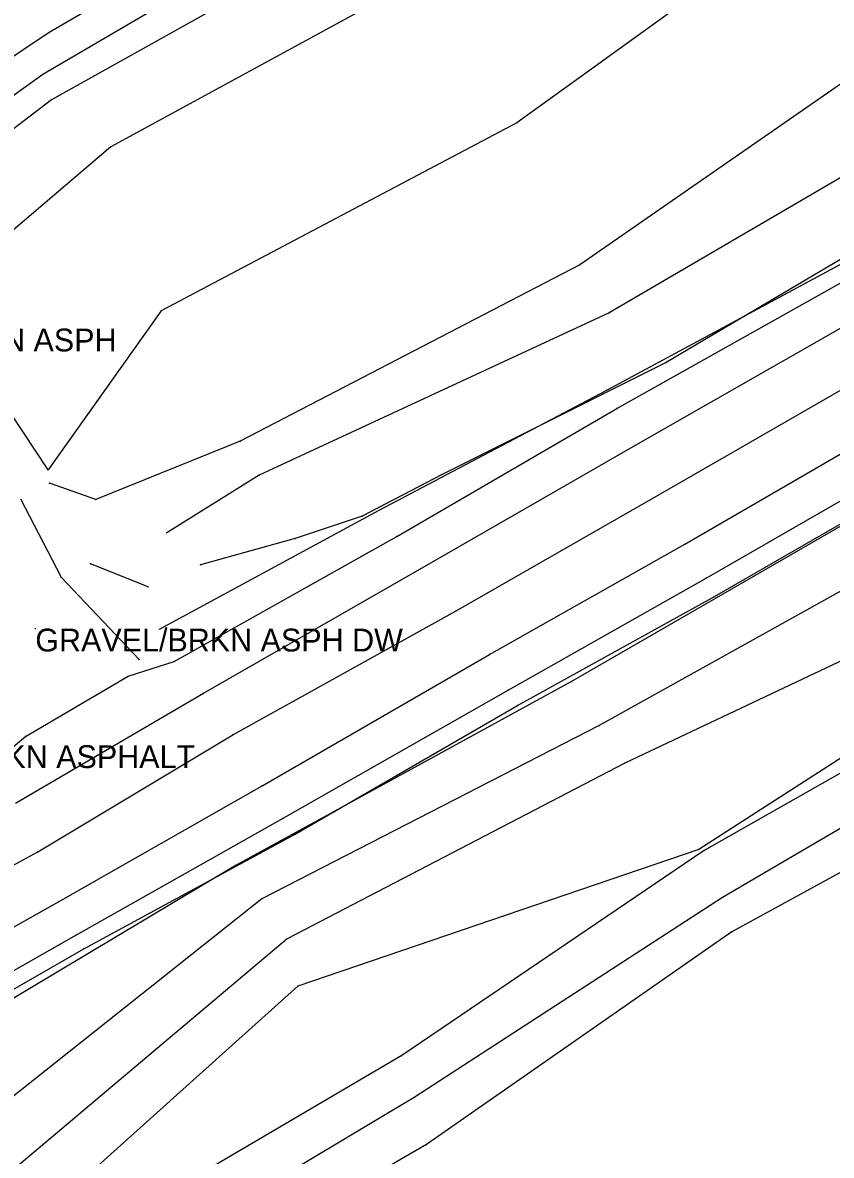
# Model space of a CAD drawing. Extents: x 1419505 to 1434054, y 1956910 to 1968644.
# Drawn here: x 1423426 to 1423603.3, y 1959101.1 to 1959349.3 of the extents above; entities that cross this region are included whole.
import ezdxf

# ---------------------------------------------------------------- set-up
doc = ezdxf.new("R2010")
doc.units = 0
for name, color, linetype in [('S_BREAKLINE', 7, 'Continuous'), ('S_DITCHLINE', 7, 'Continuous'), ('S_DRIVEWAY', 7, 'Continuous'), ('S_DRIVEWAY_ANNOT', 7, 'Continuous'), ('S_EDGE_PAVEMENT', 7, 'Continuous'), ('S_GRD_PT_SYM', 7, 'Continuous'), ('S_MSC_PT_SYM', 7, 'Continuous'), ('S_PAVEMENT_CROWN', 7, 'Continuous'), ('S_RDW_PT_SYM', 7, 'Continuous'), ('S_SHOULDER', 7, 'Continuous'), ('S_SURVEY_TEXT_ANNOT', 7, 'Continuous')]:
    doc.layers.add(name, color=color, linetype=linetype)

msp = doc.modelspace()

# ---------------------------------------------------------------- linework, layer by layer
at = {"layer": 'S_BREAKLINE'}
for p, q in [((1423507.0107, 1959374.1404), (1423432.3018, 1959332.4447)), ((1423598.1405, 1959373.3034), (1423534.3444, 1959327.3684)), ((1423515.8552, 1959360.5385), (1423445.3007, 1959322.0911)), ((1423617.2978, 1959344.1385), (1423548.1653, 1959296.2644)), ((1423432.3018, 1959332.4447), (1423394.0694, 1959303.2168)), ((1423534.3444, 1959327.3684), (1423456.3434, 1959286.1857)), ((1423625.4253, 1959327.0984), (1423554.6027, 1959285.7077)), ((1423445.3007, 1959322.0911), (1423416.7178, 1959297.7635)), ((1423633.4068, 1959314.0375), (1423567.1095, 1959274.87)), ((1423554.0877, 1959268.7666), (1423610.4613, 1959299.1086)), ((1423548.1653, 1959296.2644), (1423473.6845, 1959257.5739)), ((1423456.3434, 1959286.1857), (1423431.5548, 1959251.3445)), ((1423554.6027, 1959285.7077), (1423477.8778, 1959250.1254)), ((1423431.5548, 1959251.3445), (1423409.3454, 1959284.8777)), ((1423567.1095, 1959274.87), (1423517.9574, 1959250.2694)), ((1423504.1975, 1959242.4739), (1423554.0877, 1959268.7666)), ((1423473.6845, 1959257.5739), (1423442.0165, 1959244.8561)), ((1423627.3024, 1959251.6155), (1423546.3592, 1959204.9295)), ((1423577.7382, 1959223.5517), (1423626.5424, 1959251.6805)), ((1423442.0165, 1959244.8561), (1423431.8328, 1959248.4073)), ((1423477.8778, 1959250.1254), (1423457.5655, 1959237.5506)), ((1423517.9574, 1959250.2694), (1423500.4342, 1959241.1398)), ((1423456.0254, 1959216.4252), (1423504.1975, 1959242.4739)), ((1423500.4342, 1959241.1398), (1423485.7493, 1959236.3075)), ((1423633.2968, 1959240.3308), (1423552.4576, 1959195.2769)), ((1423485.7493, 1959236.3075), (1423465.0039, 1959230.4911)), ((1423453.4842, 1959225.6568), (1423440.8484, 1959230.7452)), ((1423642.5494, 1959226.9049), (1423558.039, 1959187.0693)), ((1423534.5064, 1959199.6852), (1423577.7382, 1959223.5517)), ((1423546.3592, 1959204.9295), (1423472.7794, 1959164.6929)), ((1423655.6463, 1959202.1823), (1423579.4483, 1959157.5964)), ((1423485.5793, 1959171.3943), (1423534.5064, 1959199.6852)), ((1423552.4576, 1959195.2769), (1423478.4158, 1959157.2674)), ((1423661.9817, 1959194.0338), (1423581.5465, 1959150.057)), ((1423558.039, 1959187.0693), (1423483.9612, 1959148.5579)), ((1423439.3733, 1959146.3467), (1423485.5793, 1959171.3943)), ((1423472.7794, 1959164.6929), (1423404.08, 1959123.6312)), ((1423478.4158, 1959157.2674), (1423414.3837, 1959106.4521)), ((1423579.4483, 1959157.5964), (1423511.876, 1959113.7706)), ((1423581.5465, 1959150.057), (1423514.5431, 1959103.4839)), ((1423412.8916, 1959131.0967), (1423439.3733, 1959146.3467)), ((1423483.9612, 1959148.5579), (1423419.455, 1959094.2393)), ((1423511.876, 1959113.7706), (1423435.8811, 1959068.4857)), ((1423514.5431, 1959103.4839), (1423441.2794, 1959060.9832))]:
    msp.add_line(p, q, dxfattribs=at)
at = {"layer": 'S_DITCHLINE'}
for p, q in [((1423500.8393, 1959387.3443), (1423431.7848, 1959347.1597)), ((1423503.4494, 1959380.6948), (1423430.4317, 1959337.9941)), ((1423431.7848, 1959347.1597), (1423383.7177, 1959315.2086)), ((1423430.4317, 1959337.9941), (1423390.0321, 1959308.9862)), ((1423648.1638, 1959215.5822), (1423574.263, 1959168.1471)), ((1423651.375, 1959211.0559), (1423575.4791, 1959167.9211)), ((1423574.263, 1959168.1471), (1423486.2963, 1959138.1412)), ((1423575.4791, 1959167.9211), (1423509.1638, 1959122.9912)), ((1423486.2963, 1959138.1412), (1423426.1714, 1959084.2167)), ((1423509.1638, 1959122.9912), (1423431.0428, 1959077.1912))]:
    msp.add_line(p, q, dxfattribs=at)
at = {"layer": 'S_DRIVEWAY'}
for p, q in [((1423425.4984, 1959244.9341), (1423434.41, 1959227.774)), ((1423434.41, 1959227.774), (1423451.4981, 1959209.7318))]:
    msp.add_line(p, q, dxfattribs=at)
at = {"layer": 'S_EDGE_PAVEMENT'}
for p, q in [((1423560.4201, 1959256.7308), (1423615.9457, 1959288.4599)), ((1423571.2408, 1959235.0654), (1423620.903, 1959263.7863)), ((1423513.1051, 1959229.5281), (1423560.4201, 1959256.7308)), ((1423528.338, 1959210.8249), (1423571.2408, 1959235.0654)), ((1423465.613, 1959202.4093), (1423513.1051, 1959229.5281)), ((1423478.4798, 1959182.074), (1423528.338, 1959210.8249)), ((1423424.3883, 1959178.2548), (1423465.613, 1959202.4093)), ((1423433.8469, 1959156.6184), (1423478.4798, 1959182.074)), ((1423406.3952, 1959141.3454), (1423433.8469, 1959156.6184))]:
    msp.add_line(p, q, dxfattribs=at)
at = {"layer": 'S_GRD_PT_SYM'}
for points in [[(1423431.7848, 1959347.1597), (1423431.7848, 1959347.2097), (1423431.7848, 1959347.1597), (1423431.7348, 1959347.1597), (1423431.7848, 1959347.1597), (1423431.7848, 1959347.1097), (1423431.7848, 1959347.1597), (1423431.8348, 1959347.1597)], [(1423430.4317, 1959337.9941), (1423430.4317, 1959338.0441), (1423430.4317, 1959337.9941), (1423430.3817, 1959337.9941), (1423430.4317, 1959337.9941), (1423430.4317, 1959337.9441), (1423430.4317, 1959337.9941), (1423430.4817, 1959337.9941)], [(1423432.3018, 1959332.4447), (1423432.3018, 1959332.4947), (1423432.3018, 1959332.4447), (1423432.2518, 1959332.4447), (1423432.3018, 1959332.4447), (1423432.3018, 1959332.3947), (1423432.3018, 1959332.4447), (1423432.3518, 1959332.4447)], [(1423534.3444, 1959327.3684), (1423534.3444, 1959327.4184), (1423534.3444, 1959327.3684), (1423534.2944, 1959327.3684), (1423534.3444, 1959327.3684), (1423534.3444, 1959327.3184), (1423534.3444, 1959327.3684), (1423534.3944, 1959327.3684)], [(1423445.3007, 1959322.0911), (1423445.3007, 1959322.1411), (1423445.3007, 1959322.0911), (1423445.2507, 1959322.0911), (1423445.3007, 1959322.0911), (1423445.3007, 1959322.0411), (1423445.3007, 1959322.0911), (1423445.3507, 1959322.0911)], [(1423548.1653, 1959296.2644), (1423548.1653, 1959296.3144), (1423548.1653, 1959296.2644), (1423548.1153, 1959296.2644), (1423548.1653, 1959296.2644), (1423548.1653, 1959296.2144), (1423548.1653, 1959296.2644), (1423548.2153, 1959296.2644)], [(1423456.3434, 1959286.1857), (1423456.3434, 1959286.2357), (1423456.3434, 1959286.1857), (1423456.2934, 1959286.1857), (1423456.3434, 1959286.1857), (1423456.3434, 1959286.1357), (1423456.3434, 1959286.1857), (1423456.3934, 1959286.1857)], [(1423554.6027, 1959285.7077), (1423554.6027, 1959285.7577), (1423554.6027, 1959285.7077), (1423554.5527, 1959285.7077), (1423554.6027, 1959285.7077), (1423554.6027, 1959285.6577), (1423554.6027, 1959285.7077), (1423554.6527, 1959285.7077)], [(1423567.1095, 1959274.87), (1423567.1095, 1959274.92), (1423567.1095, 1959274.87), (1423567.0595, 1959274.87), (1423567.1095, 1959274.87), (1423567.1095, 1959274.82), (1423567.1095, 1959274.87), (1423567.1595, 1959274.87)], [(1423554.0877, 1959268.7666), (1423554.0877, 1959268.8166), (1423554.0877, 1959268.7666), (1423554.0377, 1959268.7666), (1423554.0877, 1959268.7666), (1423554.0877, 1959268.7166), (1423554.0877, 1959268.7666), (1423554.1377, 1959268.7666)], [(1423473.6845, 1959257.5739), (1423473.6845, 1959257.6239), (1423473.6845, 1959257.5739), (1423473.6345, 1959257.5739), (1423473.6845, 1959257.5739), (1423473.6845, 1959257.5239), (1423473.6845, 1959257.5739), (1423473.7345, 1959257.5739)], [(1423431.5548, 1959251.3445), (1423431.5548, 1959251.3945), (1423431.5548, 1959251.3445), (1423431.5048, 1959251.3445), (1423431.5548, 1959251.3445), (1423431.5548, 1959251.2945), (1423431.5548, 1959251.3445), (1423431.6048, 1959251.3445)], [(1423431.8328, 1959248.4073), (1423431.8328, 1959248.4573), (1423431.8328, 1959248.4073), (1423431.7828, 1959248.4073), (1423431.8328, 1959248.4073), (1423431.8328, 1959248.3573), (1423431.8328, 1959248.4073), (1423431.8828, 1959248.4073)], [(1423477.8778, 1959250.1254), (1423477.8778, 1959250.1754), (1423477.8778, 1959250.1254), (1423477.8278, 1959250.1254), (1423477.8778, 1959250.1254), (1423477.8778, 1959250.0754), (1423477.8778, 1959250.1254), (1423477.9278, 1959250.1254)], [(1423517.9574, 1959250.2694), (1423517.9574, 1959250.3194), (1423517.9574, 1959250.2694), (1423517.9074, 1959250.2694), (1423517.9574, 1959250.2694), (1423517.9574, 1959250.2194), (1423517.9574, 1959250.2694), (1423518.0074, 1959250.2694)], [(1423442.0165, 1959244.8561), (1423442.0165, 1959244.9061), (1423442.0165, 1959244.8561), (1423441.9665, 1959244.8561), (1423442.0165, 1959244.8561), (1423442.0165, 1959244.8061), (1423442.0165, 1959244.8561), (1423442.0665, 1959244.8561)], [(1423500.4342, 1959241.1398), (1423500.4342, 1959241.1898), (1423500.4342, 1959241.1398), (1423500.3842, 1959241.1398), (1423500.4342, 1959241.1398), (1423500.4342, 1959241.0898), (1423500.4342, 1959241.1398), (1423500.4842, 1959241.1398)], [(1423504.1975, 1959242.4739), (1423504.1975, 1959242.5239), (1423504.1975, 1959242.4739), (1423504.1475, 1959242.4739), (1423504.1975, 1959242.4739), (1423504.1975, 1959242.4239), (1423504.1975, 1959242.4739), (1423504.2475, 1959242.4739)], [(1423457.5655, 1959237.5506), (1423457.5655, 1959237.6006), (1423457.5655, 1959237.5506), (1423457.5155, 1959237.5506), (1423457.5655, 1959237.5506), (1423457.5655, 1959237.5006), (1423457.5655, 1959237.5506), (1423457.6155, 1959237.5506)], [(1423485.7493, 1959236.3075), (1423485.7493, 1959236.3575), (1423485.7493, 1959236.3075), (1423485.6993, 1959236.3075), (1423485.7493, 1959236.3075), (1423485.7493, 1959236.2575), (1423485.7493, 1959236.3075), (1423485.7993, 1959236.3075)], [(1423440.8484, 1959230.7452), (1423440.8484, 1959230.7952), (1423440.8484, 1959230.7452), (1423440.7984, 1959230.7452), (1423440.8484, 1959230.7452), (1423440.8484, 1959230.6952), (1423440.8484, 1959230.7452), (1423440.8984, 1959230.7452)], [(1423465.0039, 1959230.4911), (1423465.0039, 1959230.5411), (1423465.0039, 1959230.4911), (1423464.9539, 1959230.4911), (1423465.0039, 1959230.4911), (1423465.0039, 1959230.4411), (1423465.0039, 1959230.4911), (1423465.0539, 1959230.4911)], [(1423453.4842, 1959225.6568), (1423453.4842, 1959225.7068), (1423453.4842, 1959225.6568), (1423453.4342, 1959225.6568), (1423453.4842, 1959225.6568), (1423453.4842, 1959225.6068), (1423453.4842, 1959225.6568), (1423453.5342, 1959225.6568)], [(1423577.7382, 1959223.5517), (1423577.7382, 1959223.6017), (1423577.7382, 1959223.5517), (1423577.6882, 1959223.5517), (1423577.7382, 1959223.5517), (1423577.7382, 1959223.5017), (1423577.7382, 1959223.5517), (1423577.7882, 1959223.5517)], [(1423456.0254, 1959216.4252), (1423456.0254, 1959216.4752), (1423456.0254, 1959216.4252), (1423455.9754, 1959216.4252), (1423456.0254, 1959216.4252), (1423456.0254, 1959216.3752), (1423456.0254, 1959216.4252), (1423456.0754, 1959216.4252)], [(1423546.3592, 1959204.9295), (1423546.3592, 1959204.9795), (1423546.3592, 1959204.9295), (1423546.3092, 1959204.9295), (1423546.3592, 1959204.9295), (1423546.3592, 1959204.8795), (1423546.3592, 1959204.9295), (1423546.4092, 1959204.9295)], [(1423534.5064, 1959199.6852), (1423534.5064, 1959199.7352), (1423534.5064, 1959199.6852), (1423534.4564, 1959199.6852), (1423534.5064, 1959199.6852), (1423534.5064, 1959199.6352), (1423534.5064, 1959199.6852), (1423534.5564, 1959199.6852)], [(1423552.4576, 1959195.2769), (1423552.4576, 1959195.3269), (1423552.4576, 1959195.2769), (1423552.4076, 1959195.2769), (1423552.4576, 1959195.2769), (1423552.4576, 1959195.2269), (1423552.4576, 1959195.2769), (1423552.5076, 1959195.2769)], [(1423558.039, 1959187.0693), (1423558.039, 1959187.1193), (1423558.039, 1959187.0693), (1423557.989, 1959187.0693), (1423558.039, 1959187.0693), (1423558.039, 1959187.0193), (1423558.039, 1959187.0693), (1423558.089, 1959187.0693)], [(1423485.5793, 1959171.3943), (1423485.5793, 1959171.4443), (1423485.5793, 1959171.3943), (1423485.5293, 1959171.3943), (1423485.5793, 1959171.3943), (1423485.5793, 1959171.3443), (1423485.5793, 1959171.3943), (1423485.6293, 1959171.3943)], [(1423574.263, 1959168.1471), (1423574.263, 1959168.1971), (1423574.263, 1959168.1471), (1423574.213, 1959168.1471), (1423574.263, 1959168.1471), (1423574.263, 1959168.0971), (1423574.263, 1959168.1471), (1423574.313, 1959168.1471)], [(1423575.4791, 1959167.9211), (1423575.4791, 1959167.9711), (1423575.4791, 1959167.9211), (1423575.4291, 1959167.9211), (1423575.4791, 1959167.9211), (1423575.4791, 1959167.8711), (1423575.4791, 1959167.9211), (1423575.5291, 1959167.9211)], [(1423472.7794, 1959164.6929), (1423472.7794, 1959164.7429), (1423472.7794, 1959164.6929), (1423472.7294, 1959164.6929), (1423472.7794, 1959164.6929), (1423472.7794, 1959164.6429), (1423472.7794, 1959164.6929), (1423472.8294, 1959164.6929)], [(1423478.4158, 1959157.2674), (1423478.4158, 1959157.3174), (1423478.4158, 1959157.2674), (1423478.3658, 1959157.2674), (1423478.4158, 1959157.2674), (1423478.4158, 1959157.2174), (1423478.4158, 1959157.2674), (1423478.4658, 1959157.2674)], [(1423579.4483, 1959157.5964), (1423579.4483, 1959157.6464), (1423579.4483, 1959157.5964), (1423579.3983, 1959157.5964), (1423579.4483, 1959157.5964), (1423579.4483, 1959157.5464), (1423579.4483, 1959157.5964), (1423579.4983, 1959157.5964)], [(1423581.5465, 1959150.057), (1423581.5465, 1959150.107), (1423581.5465, 1959150.057), (1423581.4965, 1959150.057), (1423581.5465, 1959150.057), (1423581.5465, 1959150.007), (1423581.5465, 1959150.057), (1423581.5965, 1959150.057)], [(1423439.3733, 1959146.3467), (1423439.3733, 1959146.3967), (1423439.3733, 1959146.3467), (1423439.3233, 1959146.3467), (1423439.3733, 1959146.3467), (1423439.3733, 1959146.2967), (1423439.3733, 1959146.3467), (1423439.4233, 1959146.3467)], [(1423483.9612, 1959148.5579), (1423483.9612, 1959148.6079), (1423483.9612, 1959148.5579), (1423483.9112, 1959148.5579), (1423483.9612, 1959148.5579), (1423483.9612, 1959148.5079), (1423483.9612, 1959148.5579), (1423484.0112, 1959148.5579)], [(1423486.2963, 1959138.1412), (1423486.2963, 1959138.1912), (1423486.2963, 1959138.1412), (1423486.2463, 1959138.1412), (1423486.2963, 1959138.1412), (1423486.2963, 1959138.0912), (1423486.2963, 1959138.1412), (1423486.3463, 1959138.1412)], [(1423509.1638, 1959122.9912), (1423509.1638, 1959123.0412), (1423509.1638, 1959122.9912), (1423509.1138, 1959122.9912), (1423509.1638, 1959122.9912), (1423509.1638, 1959122.9412), (1423509.1638, 1959122.9912), (1423509.2138, 1959122.9912)], [(1423511.876, 1959113.7706), (1423511.876, 1959113.8206), (1423511.876, 1959113.7706), (1423511.826, 1959113.7706), (1423511.876, 1959113.7706), (1423511.876, 1959113.7206), (1423511.876, 1959113.7706), (1423511.926, 1959113.7706)], [(1423514.5431, 1959103.4839), (1423514.5431, 1959103.5339), (1423514.5431, 1959103.4839), (1423514.4931, 1959103.4839), (1423514.5431, 1959103.4839), (1423514.5431, 1959103.4339), (1423514.5431, 1959103.4839), (1423514.5931, 1959103.4839)]]:
    msp.add_lwpolyline(points, dxfattribs=at)
at = {"layer": 'S_MSC_PT_SYM'}
msp.add_lwpolyline([(1423428.7566, 1959216.5152), (1423428.7566, 1959216.5652), (1423428.7566, 1959216.5152), (1423428.7066, 1959216.5152), (1423428.7566, 1959216.5152), (1423428.7566, 1959216.4652), (1423428.7566, 1959216.5152), (1423428.8066, 1959216.5152)], dxfattribs=at)
at = {"layer": 'S_PAVEMENT_CROWN'}
for p, q in [((1423565.3864, 1959245.7431), (1423620.637, 1959277.6432)), ((1423521.0396, 1959220.4225), (1423565.3864, 1959245.7431)), ((1423472.0774, 1959193.2547), (1423521.0396, 1959220.4225)), ((1423429.3166, 1959167.6311), (1423472.0774, 1959193.2547)), ((1423400.1828, 1959151.7261), (1423429.3166, 1959167.6311))]:
    msp.add_line(p, q, dxfattribs=at)
at = {"layer": 'S_RDW_PT_SYM'}
for points in [[(1423556.2988, 1959264.7534), (1423556.2988, 1959264.8034), (1423556.2988, 1959264.7534), (1423556.2488, 1959264.7534), (1423556.2988, 1959264.7534), (1423556.2988, 1959264.7034), (1423556.2988, 1959264.7534), (1423556.3488, 1959264.7534)], [(1423560.4201, 1959256.7308), (1423560.4201, 1959256.7808), (1423560.4201, 1959256.7308), (1423560.3701, 1959256.7308), (1423560.4201, 1959256.7308), (1423560.4201, 1959256.6808), (1423560.4201, 1959256.7308), (1423560.4701, 1959256.7308)], [(1423565.3864, 1959245.7431), (1423565.3864, 1959245.7931), (1423565.3864, 1959245.7431), (1423565.3364, 1959245.7431), (1423565.3864, 1959245.7431), (1423565.3864, 1959245.6931), (1423565.3864, 1959245.7431), (1423565.4364, 1959245.7431)], [(1423508.0527, 1959236.7395), (1423508.0527, 1959236.7895), (1423508.0527, 1959236.7395), (1423508.0027, 1959236.7395), (1423508.0527, 1959236.7395), (1423508.0527, 1959236.6895), (1423508.0527, 1959236.7395), (1423508.1027, 1959236.7395)], [(1423571.2408, 1959235.0654), (1423571.2408, 1959235.1154), (1423571.2408, 1959235.0654), (1423571.1908, 1959235.0654), (1423571.2408, 1959235.0654), (1423571.2408, 1959235.0154), (1423571.2408, 1959235.0654), (1423571.2908, 1959235.0654)], [(1423513.1051, 1959229.5281), (1423513.1051, 1959229.5781), (1423513.1051, 1959229.5281), (1423513.0551, 1959229.5281), (1423513.1051, 1959229.5281), (1423513.1051, 1959229.4781), (1423513.1051, 1959229.5281), (1423513.1551, 1959229.5281)], [(1423434.41, 1959227.774), (1423434.41, 1959227.824), (1423434.41, 1959227.774), (1423434.36, 1959227.774), (1423434.41, 1959227.774), (1423434.41, 1959227.724), (1423434.41, 1959227.774), (1423434.46, 1959227.774)], [(1423575.8991, 1959227.585), (1423575.8991, 1959227.635), (1423575.8991, 1959227.585), (1423575.8491, 1959227.585), (1423575.8991, 1959227.585), (1423575.8991, 1959227.535), (1423575.8991, 1959227.585), (1423575.9491, 1959227.585)], [(1423521.0396, 1959220.4225), (1423521.0396, 1959220.4725), (1423521.0396, 1959220.4225), (1423520.9896, 1959220.4225), (1423521.0396, 1959220.4225), (1423521.0396, 1959220.3725), (1423521.0396, 1959220.4225), (1423521.0896, 1959220.4225)], [(1423528.338, 1959210.8249), (1423528.338, 1959210.8749), (1423528.338, 1959210.8249), (1423528.288, 1959210.8249), (1423528.338, 1959210.8249), (1423528.338, 1959210.7749), (1423528.338, 1959210.8249), (1423528.388, 1959210.8249)], [(1423451.4981, 1959209.7318), (1423451.4981, 1959209.7818), (1423451.4981, 1959209.7318), (1423451.4481, 1959209.7318), (1423451.4981, 1959209.7318), (1423451.4981, 1959209.6818), (1423451.4981, 1959209.7318), (1423451.5481, 1959209.7318)], [(1423459.1746, 1959209.2978), (1423459.1746, 1959209.3478), (1423459.1746, 1959209.2978), (1423459.1246, 1959209.2978), (1423459.1746, 1959209.2978), (1423459.1746, 1959209.2478), (1423459.1746, 1959209.2978), (1423459.2246, 1959209.2978)], [(1423449.1429, 1959206.1296), (1423449.1429, 1959206.1796), (1423449.1429, 1959206.1296), (1423449.0929, 1959206.1296), (1423449.1429, 1959206.1296), (1423449.1429, 1959206.0796), (1423449.1429, 1959206.1296), (1423449.1929, 1959206.1296)], [(1423465.613, 1959202.4093), (1423465.613, 1959202.4593), (1423465.613, 1959202.4093), (1423465.563, 1959202.4093), (1423465.613, 1959202.4093), (1423465.613, 1959202.3593), (1423465.613, 1959202.4093), (1423465.663, 1959202.4093)], [(1423532.4283, 1959203.0424), (1423532.4283, 1959203.0924), (1423532.4283, 1959203.0424), (1423532.3783, 1959203.0424), (1423532.4283, 1959203.0424), (1423532.4283, 1959202.9924), (1423532.4283, 1959203.0424), (1423532.4783, 1959203.0424)], [(1423426.5775, 1959192.8897), (1423426.5775, 1959192.9397), (1423426.5775, 1959192.8897), (1423426.5275, 1959192.8897), (1423426.5775, 1959192.8897), (1423426.5775, 1959192.8397), (1423426.5775, 1959192.8897), (1423426.6275, 1959192.8897)], [(1423472.0774, 1959193.2547), (1423472.0774, 1959193.3047), (1423472.0774, 1959193.2547), (1423472.0274, 1959193.2547), (1423472.0774, 1959193.2547), (1423472.0774, 1959193.2047), (1423472.0774, 1959193.2547), (1423472.1274, 1959193.2547)], [(1423478.4798, 1959182.074), (1423478.4798, 1959182.124), (1423478.4798, 1959182.074), (1423478.4298, 1959182.074), (1423478.4798, 1959182.074), (1423478.4798, 1959182.024), (1423478.4798, 1959182.074), (1423478.5298, 1959182.074)], [(1423483.1421, 1959175.0006), (1423483.1421, 1959175.0506), (1423483.1421, 1959175.0006), (1423483.0921, 1959175.0006), (1423483.1421, 1959175.0006), (1423483.1421, 1959174.9506), (1423483.1421, 1959175.0006), (1423483.1921, 1959175.0006)], [(1423429.3166, 1959167.6311), (1423429.3166, 1959167.6811), (1423429.3166, 1959167.6311), (1423429.2666, 1959167.6311), (1423429.3166, 1959167.6311), (1423429.3166, 1959167.5811), (1423429.3166, 1959167.6311), (1423429.3666, 1959167.6311)], [(1423433.8469, 1959156.6184), (1423433.8469, 1959156.6684), (1423433.8469, 1959156.6184), (1423433.7969, 1959156.6184), (1423433.8469, 1959156.6184), (1423433.8469, 1959156.5684), (1423433.8469, 1959156.6184), (1423433.8969, 1959156.6184)], [(1423437.8082, 1959149.3979), (1423437.8082, 1959149.4479), (1423437.8082, 1959149.3979), (1423437.7582, 1959149.3979), (1423437.8082, 1959149.3979), (1423437.8082, 1959149.3479), (1423437.8082, 1959149.3979), (1423437.8582, 1959149.3979)]]:
    msp.add_lwpolyline(points, dxfattribs=at)
at = {"layer": 'S_SHOULDER'}
for p, q in [((1423556.2988, 1959264.7534), (1423612.1404, 1959296.1154)), ((1423508.0527, 1959236.7395), (1423556.2988, 1959264.7534)), ((1423575.8991, 1959227.585), (1423623.6012, 1959255.0417)), ((1423459.1746, 1959209.2978), (1423508.0527, 1959236.7395)), ((1423532.4283, 1959203.0424), (1423575.8991, 1959227.585)), ((1423449.1429, 1959206.1296), (1423459.1746, 1959209.2978)), ((1423426.5775, 1959192.8897), (1423449.1429, 1959206.1296)), ((1423483.1421, 1959175.0006), (1423532.4283, 1959203.0424)), ((1423417.0388, 1959184.9512), (1423426.5775, 1959192.8897)), ((1423437.8082, 1959149.3979), (1423483.1421, 1959175.0006)), ((1423410.9445, 1959134.1199), (1423437.8082, 1959149.3979))]:
    msp.add_line(p, q, dxfattribs=at)

# ---------------------------------------------------------------- texts
at = {"layer": 'S_DRIVEWAY_ANNOT'}
for s, p in [('TY:GRAVEL/BROKEN ASPH', (1423358.8791, 1959277.2775)), ('TY:GRAVEL/BROKN ASPHALT', (1423368.3205, 1959185.9666))]:
    msp.add_text(s, height=5, dxfattribs=at).set_placement(p)
at = {"layer": 'S_SURVEY_TEXT_ANNOT'}
msp.add_text('GRAVEL/BRKN ASPH DW', height=5, dxfattribs=at).set_placement((1423428.7566, 1959211.5152))

doc.saveas('drawing.dxf')
